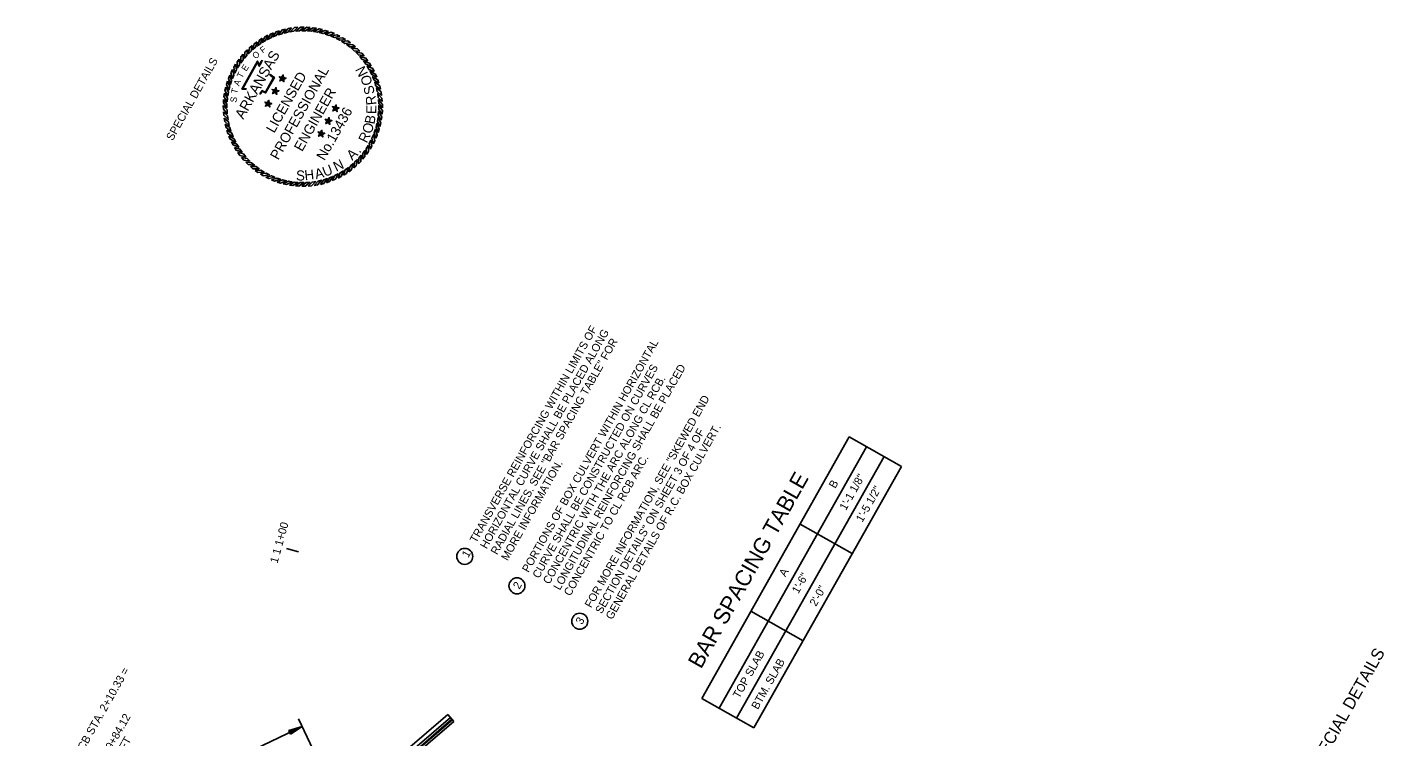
# Model space of a CAD drawing. Extents: x 992322 to 992796, y 1839560 to 1840070.
# Drawn here: x 992470.8 to 992796.4, y 1839899.8 to 1840070 of the extents above; entities that cross this region are included whole.
import ezdxf

# ---------------------------------------------------------------- set-up
doc = ezdxf.new("R2010")
doc.units = 0
for name, color, linetype in [('60', 7, 'Continuous'), ('B-Gen-Hidden', 7, 'Continuous'), ('B-Gen-Object', 7, 'Continuous'), ('Default', 7, 'Continuous'), ('G-ANNO-SYMB', 7, 'Continuous'), ('G-ANNO-TEXT', 7, 'Continuous'), ('R_Draft', 7, 'Continuous')]:
    doc.layers.add(name, color=color, linetype=linetype)

msp = doc.modelspace()

# ---------------------------------------------------------------- linework, layer by layer
at = {"layer": 'B-Gen-Hidden'}
msp.add_line((992560.13, 1839893.08), (992572.75, 1839904), dxfattribs=at)
at = {"layer": 'B-Gen-Object'}
for p, q in [((992555.23, 1839890.97), (992571.78, 1839905.14)), ((992558.71, 1839892.64), (992572.43, 1839904.38)), ((992559.57, 1839892.49), (992572.86, 1839903.87)), ((992573.19, 1839903.49), (992571.78, 1839905.14)), ((992560.7, 1839892.7), (992573.19, 1839903.49))]:
    msp.add_line(p, q, dxfattribs=at)
at = {"layer": 'G-ANNO-SYMB'}
for points in [[(992534.26, 1840069.83), (992533.45, 1840069.7), (992532.49, 1840068.59), (992533.35, 1840068.79)], [(992535.75, 1840069.99), (992534.93, 1840069.92), (992533.89, 1840068.89), (992534.77, 1840069.02)], [(992537.25, 1840070.02), (992536.43, 1840070.02), (992535.31, 1840069.08), (992536.19, 1840069.14)], [(992538.74, 1840069.94), (992537.92, 1840070), (992536.73, 1840069.15), (992537.62, 1840069.14)], [(992540.23, 1840069.75), (992539.42, 1840069.87), (992538.16, 1840069.11), (992539.05, 1840069.03)], [(992525.98, 1840066.53), (992525.31, 1840066.05), (992524.96, 1840064.63), (992525.64, 1840065.2)], [(992527.23, 1840067.35), (992526.54, 1840066.92), (992526.07, 1840065.53), (992526.8, 1840066.04)], [(992528.55, 1840068.06), (992527.82, 1840067.69), (992527.25, 1840066.34), (992528.01, 1840066.79)], [(992529.92, 1840068.67), (992529.17, 1840068.35), (992528.49, 1840067.05), (992529.29, 1840067.45)], [(992531.33, 1840069.17), (992530.56, 1840068.91), (992529.78, 1840067.67), (992530.6, 1840068)], [(992532.78, 1840069.56), (992531.99, 1840069.36), (992531.12, 1840068.18), (992531.96, 1840068.45)], [(992541.7, 1840069.43), (992540.9, 1840069.62), (992539.59, 1840068.97), (992540.46, 1840068.82)], [(992543.13, 1840069.01), (992542.35, 1840069.25), (992540.99, 1840068.71), (992541.85, 1840068.49)], [(992544.53, 1840068.47), (992543.77, 1840068.78), (992542.38, 1840068.34), (992543.22, 1840068.05)], [(992545.88, 1840067.82), (992545.15, 1840068.19), (992543.72, 1840067.86), (992544.54, 1840067.51)], [(992547.18, 1840067.07), (992546.48, 1840067.49), (992545.03, 1840067.28), (992545.82, 1840066.87)], [(992548.42, 1840066.22), (992547.75, 1840066.7), (992546.29, 1840066.6), (992547.04, 1840066.12)], [(992522.64, 1840063.53), (992522.11, 1840062.91), (992522.1, 1840061.44), (992522.63, 1840062.15)], [(992523.67, 1840064.62), (992523.09, 1840064.04), (992522.97, 1840062.58), (992523.55, 1840063.25)], [(992524.79, 1840065.62), (992524.17, 1840065.09), (992523.93, 1840063.64), (992524.56, 1840064.26)], [(992549.58, 1840065.28), (992548.95, 1840065.81), (992547.49, 1840065.82), (992548.2, 1840065.29)], [(992550.67, 1840064.24), (992550.08, 1840064.82), (992548.62, 1840064.95), (992549.29, 1840064.36)], [(992551.67, 1840063.13), (992551.13, 1840063.75), (992549.69, 1840063.99), (992550.31, 1840063.36)], [(992520.84, 1840061.14), (992520.42, 1840060.43), (992520.64, 1840058.99), (992521.05, 1840059.77)], [(992521.69, 1840062.37), (992521.22, 1840061.7), (992521.32, 1840060.24), (992521.79, 1840060.99)], [(992552.58, 1840061.94), (992552.09, 1840062.6), (992550.67, 1840062.95), (992551.24, 1840062.27)], [(992553.4, 1840060.68), (992552.96, 1840061.38), (992551.57, 1840061.84), (992552.09, 1840061.12)], [(992554.11, 1840059.36), (992553.73, 1840060.09), (992552.38, 1840060.66), (992552.84, 1840059.9)], [(992518.91, 1840057.09), (992518.66, 1840056.3), (992519.21, 1840054.95), (992519.43, 1840055.81)], [(992519.45, 1840058.49), (992519.14, 1840057.73), (992519.58, 1840056.33), (992519.86, 1840057.17)], [(992520.09, 1840059.84), (992519.73, 1840059.1), (992520.06, 1840057.68), (992520.4, 1840058.49)], [(992532.08, 1840057.71), (992531.94, 1840058.01), (992531.32, 1840058.14), (992531.74, 1840057.67)], [(992532.08, 1840057.71), (992531.74, 1840057.67), (992531.43, 1840057.12), (992532.01, 1840057.38)], [(992532.08, 1840057.71), (992532.32, 1840057.94), (992532.25, 1840058.57), (992531.94, 1840058.01)], [(992532.08, 1840057.71), (992532.01, 1840057.38), (992532.44, 1840056.92), (992532.37, 1840057.55)], [(992532.08, 1840057.71), (992532.37, 1840057.55), (992532.94, 1840057.81), (992532.32, 1840057.94)], [(992554.72, 1840057.99), (992554.4, 1840058.75), (992553.1, 1840059.42), (992553.49, 1840058.63)], [(992555.22, 1840056.58), (992554.96, 1840057.36), (992553.72, 1840058.13), (992554.05, 1840057.31)], [(992555.6, 1840055.13), (992555.41, 1840055.93), (992554.23, 1840056.8), (992554.49, 1840055.95)], [(992518.17, 1840054.18), (992518.05, 1840053.37), (992518.8, 1840052.12), (992518.88, 1840053)], [(992518.48, 1840055.65), (992518.29, 1840054.85), (992518.95, 1840053.54), (992519.1, 1840054.42)], [(992530.36, 1840054.67), (992530.22, 1840054.97), (992529.6, 1840055.1), (992530.03, 1840054.63)], [(992530.36, 1840054.67), (992530.03, 1840054.63), (992529.72, 1840054.08), (992530.29, 1840054.34)], [(992530.36, 1840054.67), (992530.6, 1840054.9), (992530.53, 1840055.53), (992530.22, 1840054.97)], [(992530.36, 1840054.67), (992530.29, 1840054.34), (992530.72, 1840053.88), (992530.65, 1840054.51)], [(992530.36, 1840054.67), (992530.65, 1840054.51), (992531.23, 1840054.77), (992530.6, 1840054.9)], [(992555.88, 1840053.66), (992555.74, 1840054.47), (992554.64, 1840055.43), (992554.83, 1840054.56)], [(992556.03, 1840052.17), (992555.96, 1840052.98), (992554.93, 1840054.03), (992555.06, 1840053.15)], [(992517.89, 1840051.2), (992517.9, 1840050.38), (992518.84, 1840049.26), (992518.78, 1840050.15)], [(992517.97, 1840052.7), (992517.91, 1840051.88), (992518.76, 1840050.69), (992518.77, 1840051.58)], [(992528.64, 1840051.63), (992528.51, 1840051.93), (992527.88, 1840052.06), (992528.31, 1840051.59)], [(992528.64, 1840051.63), (992528.31, 1840051.59), (992528, 1840051.04), (992528.58, 1840051.3)], [(992528.64, 1840051.63), (992528.89, 1840051.86), (992528.82, 1840052.49), (992528.51, 1840051.93)], [(992528.64, 1840051.63), (992528.58, 1840051.3), (992529.01, 1840050.84), (992528.93, 1840051.47)], [(992528.64, 1840051.63), (992528.93, 1840051.47), (992529.51, 1840051.73), (992528.89, 1840051.86)], [(992544.81, 1840050.53), (992544.67, 1840050.83), (992544.05, 1840050.96), (992544.47, 1840050.49)], [(992544.81, 1840050.53), (992544.47, 1840050.49), (992544.16, 1840049.94), (992544.74, 1840050.2)], [(992544.81, 1840050.53), (992545.05, 1840050.75), (992544.98, 1840051.38), (992544.67, 1840050.83)], [(992544.81, 1840050.53), (992544.74, 1840050.2), (992545.17, 1840049.73), (992545.1, 1840050.36)], [(992544.81, 1840050.53), (992545.1, 1840050.36), (992545.67, 1840050.63), (992545.05, 1840050.75)], [(992556.07, 1840050.67), (992556.06, 1840051.49), (992555.12, 1840052.61), (992555.18, 1840051.72)], [(992555.99, 1840049.17), (992556.05, 1840049.99), (992555.2, 1840051.18), (992555.19, 1840050.29)], [(992517.93, 1840049.7), (992518, 1840048.88), (992519.03, 1840047.84), (992518.9, 1840048.72)], [(992518.08, 1840048.21), (992518.22, 1840047.4), (992519.32, 1840046.44), (992519.13, 1840047.31)], [(992543.09, 1840047.49), (992542.95, 1840047.79), (992542.33, 1840047.92), (992542.76, 1840047.45)], [(992543.09, 1840047.49), (992542.76, 1840047.45), (992542.45, 1840046.9), (992543.02, 1840047.16)], [(992543.09, 1840047.49), (992543.34, 1840047.71), (992543.26, 1840048.34), (992542.95, 1840047.79)], [(992543.09, 1840047.49), (992543.02, 1840047.16), (992543.45, 1840046.69), (992543.38, 1840047.32)], [(992543.09, 1840047.49), (992543.38, 1840047.32), (992543.96, 1840047.59), (992543.34, 1840047.71)], [(992555.05, 1840044.78), (992555.3, 1840045.56), (992554.75, 1840046.92), (992554.53, 1840046.06)], [(992555.48, 1840046.22), (992555.67, 1840047.02), (992555.01, 1840048.33), (992554.86, 1840047.45)], [(992555.79, 1840047.68), (992555.91, 1840048.5), (992555.16, 1840049.75), (992555.08, 1840048.87)], [(992518.36, 1840046.74), (992518.55, 1840045.94), (992519.73, 1840045.07), (992519.47, 1840045.92)], [(992518.74, 1840045.29), (992519, 1840044.51), (992520.24, 1840043.74), (992519.91, 1840044.56)], [(992519.24, 1840043.88), (992519.56, 1840043.12), (992520.86, 1840042.45), (992520.47, 1840043.24)], [(992541.37, 1840044.45), (992541.24, 1840044.75), (992540.61, 1840044.87), (992541.04, 1840044.41)], [(992541.37, 1840044.45), (992541.04, 1840044.41), (992540.73, 1840043.86), (992541.31, 1840044.12)], [(992541.37, 1840044.45), (992541.62, 1840044.67), (992541.55, 1840045.3), (992541.24, 1840044.75)], [(992541.37, 1840044.45), (992541.31, 1840044.12), (992541.74, 1840043.65), (992541.66, 1840044.28)], [(992541.37, 1840044.45), (992541.66, 1840044.28), (992542.24, 1840044.55), (992541.62, 1840044.67)], [(992553.87, 1840042.03), (992554.23, 1840042.76), (992553.9, 1840044.19), (992553.56, 1840043.37)], [(992554.51, 1840043.38), (992554.82, 1840044.14), (992554.38, 1840045.54), (992554.1, 1840044.7)], [(992519.85, 1840042.51), (992520.23, 1840041.78), (992521.58, 1840041.21), (992521.12, 1840041.97)], [(992520.56, 1840041.19), (992521, 1840040.49), (992522.39, 1840040.03), (992521.87, 1840040.75)], [(992551.32, 1840038.33), (992551.85, 1840038.96), (992551.86, 1840040.43), (992551.33, 1840039.71)], [(992552.27, 1840039.5), (992552.74, 1840040.17), (992552.64, 1840041.63), (992552.17, 1840040.87)], [(992553.12, 1840040.73), (992553.54, 1840041.44), (992553.32, 1840042.88), (992552.91, 1840042.1)], [(992521.38, 1840039.93), (992521.87, 1840039.27), (992523.29, 1840038.92), (992522.72, 1840039.6)], [(992522.29, 1840038.74), (992522.83, 1840038.12), (992524.27, 1840037.88), (992523.65, 1840038.51)], [(992523.29, 1840037.62), (992523.88, 1840037.05), (992525.34, 1840036.92), (992524.67, 1840037.51)], [(992547.98, 1840035.33), (992548.65, 1840035.82), (992549, 1840037.24), (992548.32, 1840036.67)], [(992549.17, 1840036.25), (992549.79, 1840036.78), (992550.03, 1840038.23), (992549.4, 1840037.61)], [(992550.29, 1840037.25), (992550.87, 1840037.83), (992550.99, 1840039.29), (992550.41, 1840038.62)], [(992524.38, 1840036.59), (992525.01, 1840036.06), (992526.47, 1840036.05), (992525.76, 1840036.58)], [(992525.54, 1840035.65), (992526.21, 1840035.17), (992527.67, 1840035.27), (992526.92, 1840035.75)], [(992526.78, 1840034.8), (992527.48, 1840034.37), (992528.93, 1840034.59), (992528.14, 1840035)], [(992528.08, 1840034.05), (992528.81, 1840033.68), (992530.24, 1840034.01), (992529.42, 1840034.36)], [(992542.63, 1840032.7), (992543.4, 1840032.96), (992544.18, 1840034.2), (992543.36, 1840033.87)], [(992544.04, 1840033.2), (992544.79, 1840033.52), (992545.47, 1840034.81), (992544.67, 1840034.42)], [(992545.41, 1840033.8), (992546.14, 1840034.18), (992546.71, 1840035.53), (992545.95, 1840035.08)], [(992546.73, 1840034.52), (992547.42, 1840034.95), (992547.89, 1840036.34), (992547.16, 1840035.83)], [(992529.43, 1840033.4), (992530.19, 1840033.09), (992531.58, 1840033.53), (992530.74, 1840033.82)], [(992530.83, 1840032.86), (992531.61, 1840032.61), (992532.97, 1840033.16), (992532.11, 1840033.38)], [(992532.26, 1840032.43), (992533.06, 1840032.25), (992534.37, 1840032.9), (992533.5, 1840033.05)], [(992533.73, 1840032.12), (992534.54, 1840032), (992535.8, 1840032.75), (992534.91, 1840032.83)], [(992535.22, 1840031.93), (992536.04, 1840031.87), (992537.23, 1840032.72), (992536.34, 1840032.73)], [(992536.71, 1840031.85), (992537.53, 1840031.85), (992538.65, 1840032.79), (992537.77, 1840032.73)], [(992538.21, 1840031.88), (992539.03, 1840031.95), (992540.07, 1840032.98), (992539.19, 1840032.85)], [(992539.7, 1840032.04), (992540.51, 1840032.17), (992541.47, 1840033.28), (992540.61, 1840033.08)], [(992541.18, 1840032.31), (992541.97, 1840032.51), (992542.84, 1840033.69), (992542, 1840033.42)]]:
    msp.add_lwpolyline(points, close=True, dxfattribs=at)
for points in [[(992523.41, 1840055.08), (992522.35, 1840055.17), (992526.13, 1840061.88), (992526.52, 1840060.92), (992526.77, 1840061.38), (992526.98, 1840061.76), (992527.24, 1840062.12)], [(992523.42, 1840055.2), (992522.55, 1840055.27), (992526.11, 1840061.59), (992526.5, 1840060.63), (992526.88, 1840061.32), (992527.08, 1840061.69), (992527.34, 1840062.05)], [(992529.07, 1840058.74), (992529.1, 1840058.53), (992529.26, 1840058.38), (992529.6, 1840058.14), (992529.96, 1840057.93), (992527.97, 1840054.4), (992527.45, 1840054.69), (992527.23, 1840054.82), (992527.02, 1840054.62), (992526.74, 1840054.12), (992526.61, 1840054.12)], [(992529.19, 1840058.76), (992529.22, 1840058.59), (992529.34, 1840058.47), (992529.66, 1840058.24), (992530.13, 1840057.98), (992528.01, 1840054.23), (992527.39, 1840054.59), (992527.25, 1840054.67), (992527.12, 1840054.54), (992526.82, 1840054.01), (992526.62, 1840053.99)]]:
    msp.add_lwpolyline(points, dxfattribs=at)
at = {"layer": 'R_Draft'}
for p, q in [((992632.69, 1839909.01), (992668.08, 1839971.72)), ((992636.87, 1839906.65), (992672.26, 1839969.36)), ((992668.08, 1839971.72), (992680.62, 1839964.64)), ((992641.05, 1839904.29), (992676.44, 1839967)), ((992645.23, 1839901.94), (992680.62, 1839964.64)), ((992656.28, 1839950.82), (992668.82, 1839943.74)), ((992644.49, 1839929.91), (992657.03, 1839922.84)), ((992632.69, 1839909.01), (992645.23, 1839901.94)), ((992567.85, 1839837.33), (992535.92, 1839904.09)), ((992536.78, 1839902.28), (992470.81, 1839870.73)), ((992533.6, 1839901.31), (992536.78, 1839902.28)), ((992534.02, 1839900.42), (992533.6, 1839901.31)), ((992533.64, 1839901.24), (992536.29, 1839902.05)), ((992533.67, 1839901.16), (992535.77, 1839901.8)), ((992533.71, 1839901.08), (992535.28, 1839901.57)), ((992533.74, 1839901.01), (992534.78, 1839901.33)), ((992533.78, 1839900.94), (992534.29, 1839901.09)), ((992533.85, 1839900.79), (992534.29, 1839901.09)), ((992533.88, 1839900.73), (992534.78, 1839901.33)), ((992533.92, 1839900.64), (992535.28, 1839901.57)), ((992533.95, 1839900.57), (992535.77, 1839901.8)), ((992533.99, 1839900.5), (992536.29, 1839902.05)), ((992534.02, 1839900.42), (992536.78, 1839902.28))]:
    msp.add_line(p, q, dxfattribs=at)
msp.add_lwpolyline([(992533.01, 1839944.92), (992535.91, 1839944.12)], dxfattribs=at)
for centre in [(992575.82, 1839943.07), (992588.36, 1839936), (992603.41, 1839927.5)]:
    msp.add_circle(centre, 1.92, dxfattribs=at)

# ---------------------------------------------------------------- texts
at = {"layer": '60'}
msp.add_text('SPECIAL DETAILS', height=2.88, rotation=60.5619, dxfattribs=at).set_placement((992780.31, 1839890.93))
at = {"layer": 'Default'}
msp.add_text('BAR SPACING TABLE', height=3.84, rotation=60.5619, dxfattribs=at).set_placement((992632.52, 1839915.89))
at = {"layer": 'G-ANNO-SYMB'}
for s, height, rotation, p in [('ARKANSAS', 2.479, 60.5619, (992522.67, 1840047.76)), ('O', 1.52, 41.7837, (992525.64, 1840062.27)), ('F', 1.52, 35.9247, (992527.35, 1840063.66)), ('E', 1.52, 57.2339, (992523.38, 1840059.31)), ('N', 2.4, 116.6626, (992552.66, 1840058.89)), ('A', 1.52, 69.2407, (992521.68, 1840055.79)), ('T', 1.52, 62.0408, (992522.38, 1840057.64)), ('LICENSED', 2.4, 60.5619, (992530.09, 1840044.45)), ('PROFESSIONAL', 2.4, 60.5619, (992531.06, 1840038)), ('O', 2.4, 105.3376, (992553.72, 1840056.38)), ('T', 1.52, 77.4634, (992521.19, 1840053.94)), ('ENGINEER', 2.4, 60.5619, (992536.8, 1840040.01)), ('S', 2.4, 104.0497, (992554.29, 1840054.16)), ('R', 2.4, 96.2216, (992554.63, 1840051.44)), ('S', 1.52, 80.3344, (992521, 1840051.84)), ('No.13436', 2.391, 60.5619, (992542.16, 1840037.86)), ('E', 2.4, 88.3934, (992554.56, 1840049.15)), ('O', 2.4, 71.9915, (992553.38, 1840044.27)), ('B', 2.4, 79.4469, (992554.12, 1840046.61)), ('R', 2.4, 63.7906, (992552.31, 1840042.05)), ('A', 2.4, 43.661, (992548.83, 1840037.93)), ('N', 2.4, 25.4945, (992544.98, 1840035.3)), ('.', 2.4, 51.8619, (992550.6, 1840039.64)), ('S', 2.4, 358.7255, (992535.31, 1840033.26)), ('H', 2.4, 6.1809, (992537.48, 1840033.28)), ('A', 2.4, 14.0091, (992540.14, 1840033.54)), ('U', 2.4, 21.4645, (992542.24, 1840034.07))]:
    msp.add_text(s, height=height, rotation=rotation, dxfattribs=at).set_placement(p)
at = {"layer": 'G-ANNO-TEXT'}
msp.add_text('SPECIAL DETAILS', height=1.92, rotation=60.5619, dxfattribs=at).set_placement((992505.72, 1840042.62))
at = {"layer": 'R_Draft'}
for s, rotation, p in [('TRANSVERSE REINFORCING WITHIN LIMITS OF ', 60.5619, (992578.57, 1839946.13)), ('HORIZONTAL CURVE SHALL BE PLACED ALONG ', 60.5619, (992581.08, 1839944.71)), ('RADIAL LINES. SEE "BAR SPACING TABLE" FOR ', 60.5619, (992583.59, 1839943.3)), ('PORTIONS OF BOX CULVERT WITHIN HORIZONTAL ', 60.5619, (992591.12, 1839939.05)), ('CURVE SHALL BE CONSTRUCTED ON CURVES ', 60.5619, (992593.62, 1839937.63)), ('LONGITUDINAL REINFORCING SHALL BE PLACED ', 60.5619, (992598.64, 1839934.8)), ('CONCENTRIC WITH THE ARC ALONG CL RCB. ', 60.5619, (992596.13, 1839936.22)), ('FOR MORE INFORMATION, SEE "SKEWED END ', 60.5619, (992606.16, 1839930.56)), ('SECTION DETAILS" ON SHEET 3 OF 4 OF ', 60.5619, (992608.67, 1839929.14)), ('GENERAL DETAILS OF R.C. BOX CULVERT.', 60.5619, (992611.18, 1839927.73)), ('MORE INFORMATION.', 60.5619, (992586.1, 1839941.88)), ('CONCENTRIC TO CL RCB ARC.', 60.5619, (992601.15, 1839933.39)), ('1\'-1 1/8"', 60.5619, (992667.29, 1839953.95)), ('B', 60.5619, (992664.73, 1839959.22)), ('1\'-5 1/2"', 60.5619, (992671.23, 1839951.1)), ('1 1 1+00', 74.5626, (992530.88, 1839941.27)), ('1', 60.495, (992576.65, 1839942.6)), ('A', 60.5619, (992652.77, 1839938.03)), ('2', 60.495, (992588.93, 1839935.05)), ('1\'-6"', 60.5619, (992655.87, 1839933.97)), ('2\'-0"', 60.5619, (992660.11, 1839930.92)), ('3', 60.495, (992603.97, 1839926.56)), ('TOP SLAB', 60.5619, (992641.69, 1839908.84)), ('BTM. SLAB', 60.5619, (992646.15, 1839906.19)), ('PT RCB STA. 2+10.33 =', 60.5619, (992481.57, 1839891.25)), ('STA. 109+84.12', 60.5619, (992486.58, 1839888.42)), ("15.62' LEFT", 60.5619, (992489.09, 1839887))]:
    msp.add_text(s, height=1.92, rotation=rotation, dxfattribs=at).set_placement(p)

doc.saveas('drawing.dxf')
